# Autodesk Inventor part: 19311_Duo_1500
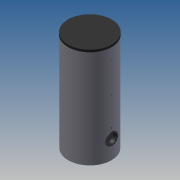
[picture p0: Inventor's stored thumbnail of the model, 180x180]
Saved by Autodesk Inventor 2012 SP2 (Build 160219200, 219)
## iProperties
description: 0:0:19311_Duo_1500
manufacturer: 0:0:Flamco Group
model: 0:0:Duo 1500
url: 0:0:www.flamcogroup.com
allow_slope_adjustment: 0 ul
connection_type: 13 ul
flow_configuration2: 1 ul
flow_direction: 2 ul
loss_method: 0 ul
radius: 12,250 mm
radius: 28,500 mm
radius: 15,375 mm
Created: 2014-05
Part Number: 19311_Duo_1500
Material: Default
Document SubType Name: Modeling
Designer: michel
Density: 1 g/cm^3
radius: 9,500 mm
Author: michel
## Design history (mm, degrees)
sketch "Sketch1"
  geometry: C1 r 500 at (0, 0); 1 further point
  constraints: 1 centre point, 1 coincident
  dimensions: "d0" = 1000 diameter of C1
extrude "Extrusion1" new body sketch "Sketch1" distance "d1" = 2320; taper "d2" = 0 deg
sketch "Sketch2"
  geometry: L1 (-500, 2320)-(500, 2320) reference; L2 (-500, 0)-(500, 0) reference; L3 (500, 0)-(500, 2320) reference; L4 (500, 2320)-(505, 2320); L5 (505, 2320)-(505, 2270); L6 (505, 2270)-(500, 2270); L7 (500, 2270)-(500, 2320); L8 (0, -446)-(0, 2676) reference; 1 further point
  constraints: 8 end point, 2 parallel, 1 horizontal, 1 perpendicular
  dimensions: "d3" = 5 distance of L5.end L6.end; "d4" = 50 distance of L4.end L5.end
revolve "Revolution1" sketch "Sketch2" stored, may be unused: angle "d5" = 90 deg
workplane "Work Plane1"
workplane "Work Plane2"
workplane "Work Plane3"
workplane "Work Plane4"
workplane "Work Plane5"
workplane "Work Plane6"
workplane "Work Plane11"
workplane "Work Plane12"
workplane "Work Plane13"
sketch "Sketch3"
  geometry: L1 (701.4, 2235)-(-701.4, 2235) reference; L2 (701.4, 1735)-(-701.4, 1735) reference; L3 (701.4, 1555)-(-701.4, 1555) reference; L4 (701.4, 435)-(-701.4, 435) reference; L5 (701.4, 85)-(-701.4, 85) reference; L6 (500, 0)-(500, 2270) reference; L7 (500, 2235)-(460, 2235); L8 (460, 2235)-(460, 2264.805); L9 (460, 2264.805)-(500, 2264.805); L10 (500, 1735)-(460, 1735); L11 (460, 1735)-(460, 1751.625); L12 (460, 1751.625)-(500, 1751.625); L13 (500, 1751.625)-(500, 1735); L14 (335, 2206.5)-(335, 2205.195); L15 (335, 2205.195)-(501, 2205.195); L16 (501, 2205.195)-(501, 2206.5); L17 (501, 2206.5)-(335, 2206.5); L18 (460, 1555)-(460, 1584.805); L19 (500, 1555)-(460, 1555); L20 (460, 1584.805)-(500, 1584.805); L21 (500, 1584.805)-(500, 1555); L22 (335, 1526.5)-(335, 1525.195); L23 (335, 1525.195)-(501, 1525.195); L24 (501, 1525.195)-(501, 1526.5); L25 (501, 1526.5)-(335, 1526.5); L26 (460, 464.805)-(500, 464.805); L27 (460, 435)-(460, 464.805); L28 (500, 435)-(460, 435); L29 (500, 464.805)-(500, 435); L30 (501, 406.5)-(335.165, 406.5); L31 (335.165, 406.5)-(335.165, 405.195); L32 (335.165, 405.195)-(501, 405.195); L33 (501, 405.195)-(501, 406.5); L34 (460, 114.805)-(500, 114.805); L35 (460, 85)-(460, 114.805); L36 (500, 85)-(460, 85); L37 (500, 114.805)-(500, 85); L38 (501, 56.5)-(335, 56.5); L39 (335, 56.5)-(335, 55.195); L40 (335, 55.195)-(501, 55.195); L41 (501, 55.195)-(501, 56.5); L42 (335, 1719.625)-(335, 1718.375); L43 (501, 1718.375)-(501, 1719.625); L44 (501, 1719.625)-(335, 1719.625); L45 (-707, 2020)-(707, 2020) reference; L46 (701.4, 1300)-(-701.4, 1300) reference; L47 (-500, 0)-(-500, 2270) reference; L48 (-500, 2020)-(-460, 2020); L49 (-460, 2020)-(-460, 2030.475); L50 (-460, 2030.475)-(-500, 2030.475); L51 (-500, 2030.475)-(-500, 2020); L52 (-501, 2009.525)-(-335, 2009.525); L53 (-335, 2009.525)-(-335, 2010.5); L54 (-335, 2010.5)-(-501, 2010.5); L55 (-501, 2010.5)-(-501, 2009.525); L56 (-500, 1300)-(-335, 1300); L57 (-335, 1300)-(-335, 1313.22); L58 (-335, 1313.22)-(-500, 1313.22); L59 (-500, 1313.22)-(-500, 1300); L60 (-501, 1286.78)-(-335, 1286.78); L61 (-335, 1286.78)-(-335, 1287.75); L62 (-335, 1287.75)-(-501, 1287.75); L63 (-501, 1287.75)-(-501, 1286.78); L64 (500, 2264.805)-(500, 2235)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; 2 further points
  constraints: 128 end point, 20 parallel, 9 horizontal, 9 perpendicular, 8 point on line, 1 collinear
  dimensions: "d19" = 40 distance of L8.end L9.end; "d21" = 40 distance of L11.end L12.end; "d70" = 29.805 distance between parallel lines of L1 L9; "d73" = 40 distance of L18.end L20.end; "d74" = 40 distance of L26.start L26.end; "d75" = 40 distance of L34.start L34.end; "d76" = 29.805 distance between parallel lines of L3 L20; "d85" = 16.625 distance between parallel lines of L2 L12; "d108" = 29.805 distance between parallel lines of L1 L15 (derived); "d109" = 1.305 distance between parallel lines of L17 L15 (derived); "d110" = 16.625 distance between parallel lines of L10 L12 (= d85); "d113" = 29.805 distance between parallel lines of L19 L20 (= d76); "d114" = 29.805 distance between parallel lines of L23 L3 (derived); "d115" = 1.305 distance between parallel lines of L25 L23 (derived); "d116" = 29.805 distance between parallel lines of L4 L26; "d117" = 29.805 distance of L26.start L27.start (= d116); "d118" = 29.805 distance between parallel lines of L32 L4 (derived); "d119" = 1.305 distance between parallel lines of L30 L32 (derived); "d120" = 29.805 distance from line of L34 L35.start (= d121); "d121" = 29.805 distance between parallel lines of L5 L34; "d122" = 29.805 distance between parallel lines of L40 L5 (derived); "d123" = 1.305 distance between parallel lines of L38 L40 (derived); "d129" = 40 distance of L50.end L49.end; "d130" = 10.475 distance of L49.end L48.end; "d131" = 10.475 distance between parallel lines of L45 L52; "d132" = 0.975 distance between parallel lines of L54 L52; "d134" = 13.22 distance between parallel lines of L46 L58; "d135" = 13.22 distance between parallel lines of L46 L60 (derived); "d136" = 0.97 distance between parallel lines of L62 L60 (derived); "d154" = 1 distance between parallel lines of L47 L55; "d155" = 1 distance between parallel lines of L47 L63; "d157" = 1 distance between parallel lines of L6 L16; "d158" = 0 distance between parallel lines of L6 L13; "d159" = 1 distance between parallel lines of L6 L43; "d160" = 0 distance between parallel lines of L6 L21; "d161" = 1 distance between parallel lines of L6 L24; "d162" = 0 distance between parallel lines of L6 L29; "d163" = 1 distance between parallel lines of L6 L33; "d164" = 0 distance between parallel lines of L6 L37; "d165" = 1 distance between parallel lines of L6 L41; "d166" = 16.625 distance between parallel lines of L65 L2 (derived); "d167" = 1.25 distance between parallel lines of L44 L65 (derived); "d173" = 0 distance between parallel lines of L6 L64; "d181" = 40 distance of L69.end L68.end; "d182" = 13.22 distance of L68.end L67.end; "d183" = 13.22 distance between parallel lines of L66 L73 (derived); "d184" = 0.97 distance between parallel lines of L71 L73 (derived); "d185" = 1 distance between parallel lines of L47 L74
revolve "Revolution2" stored, may be unused: angle "d23" = 90 deg
sketch "Sketch5"
  geometry: L1 (-500, 0)-(-500, 2270) reference; L2 (-500, 0)-(-500, 435); L3 (-220, 435)-(-594, 435); L4 (-500, 435)-(-512.5, 435); L5 (-512.5, 435)-(-512.5, 575); L6 (-512.5, 575)-(-500, 575); L7 (-500, 575)-(-500, 435); L8 (-500, 0)-(500, 0) reference; 1 further point
  constraints: 12 end point, 2 parallel, 2 perpendicular, 1 horizontal, 1 point on line
  dimensions: "d35" = 435 distance of L1.start L2.end; "d36" = 12.5 distance of L5.end L6.end; "d37" = 140 distance of L4.end L5.end; "d124" = 435 distance between parallel lines of L8 L3 (= d35)
revolve "Revolution7" sketch "Sketch5" stored, may be unused: angle "d38" = 90 deg
sketch "Sketch6"
  geometry: C1 r 122.5 at (0, 0); A1 r 140 centre (0, 0) between (140, 0) and (-140, 0) reference; 1 further point
  constraints: 1 centre point, 1 coincident
  dimensions: "d39" = 245 diameter of C1
extrude "Extrusion3" join sketch "Sketch6" stored distance "d40" = 40; taper "d41" = 0 deg
sketch "Sketch7"
  geometry: C1 r 140 at (0, 0) reference; C2 r 102.5 at (0, 0); 1 further point
  constraints: 1 centre point, 1 coincident
  dimensions: "d42" = 205 diameter of C2
extrude "Extrusion4" cut sketch "Sketch7" distance "d43" = 80; taper "d44" = 0 deg
revolve "Revolution9" stored, may be unused: angle "d69" = 90 deg
revolve "Revolution10" stored, may be unused: angle "d92" = 90 deg
revolve "Revolution11" stored, may be unused: angle "d93" = 90 deg
revolve "Revolution12" stored, may be unused: angle "d94" = 90 deg
revolve "Revolution13" stored, may be unused: angle "d95" = 90 deg
revolve "Revolution14" stored, may be unused: angle "d96" = 90 deg
revolve "Revolution15" stored, may be unused: angle "d97" = 90 deg
revolve "Revolution16" stored, may be unused: angle "d98" = 90 deg
revolve "Revolution17" stored, may be unused: angle "d99" = 90 deg
revolve "Revolution18" stored, may be unused: angle "d138" = 90 deg
revolve "Revolution19" stored, may be unused: angle "d139" = 90 deg
revolve "Revolution20" stored, may be unused: angle "d140" = 90 deg
revolve "Revolution21" stored, may be unused: angle "d141" = 90 deg
revolve "Revolution22" stored, may be unused: angle "d186" = 90 deg
revolve "Revolution23" stored, may be unused: angle "d187" = 90 deg
body "Solid1"
node "Projected Loop1"
other parameters: "d12" = 0, "d174" = -2235, "d175" = -1735, "d176" = -1555, "d177" = -435, "d178" = -85
